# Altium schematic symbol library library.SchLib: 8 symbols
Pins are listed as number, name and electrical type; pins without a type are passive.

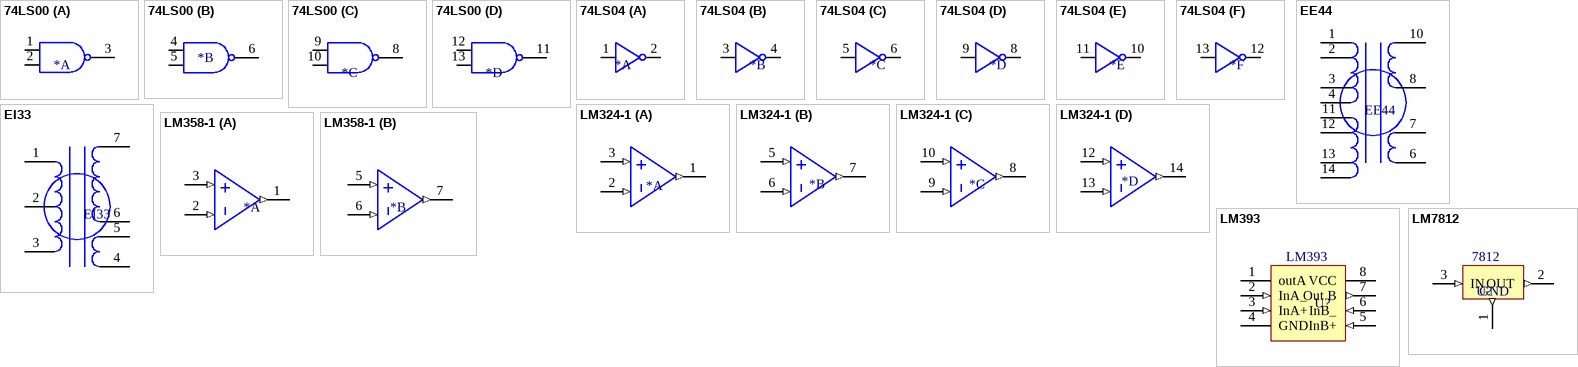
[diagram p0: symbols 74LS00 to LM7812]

## 74LS00
designator *
part A pins: 1 (power), 2 (power), 3 (power), 7 GND (power) hidden to GND, 14 VCC+5V (power) hidden to VCC+5V
part B pins: 4 (power), 5 (power), 6 (power)
part C pins: 8 (power), 9 (power), 10 (power)
part D pins: 11 (power), 12 (power), 13 (power)

## 74LS04
designator *
part A pins: 1 (power), 2 (power), 7 GND (power) hidden to GND, 14 VCC+5v (power) hidden to VCC+5V
part B pins: 3 (power), 4 (power)
part C pins: 5 (power), 6 (power)
part D pins: 8 (power), 9 (power)
part E pins: 10 (power), 11 (power)
part F pins: 12 (power), 13 (power)

## EE44
designator EE44
footprint EE44; pin to pad 10>9
pins: 1 (power), 2 (power), 3 (power), 4 (power), 6 (power), 7 (power), 8 (power), 10 (power), 11 (power), 12 (power), 13 (power), 14 (power)

## EI33
designator EI33
pins: 1 (power), 2 (power), 3 (power), 4 (power), 5 (power), 6 (power), 7 (power)

## LM324-1
designator *
part A pins: 1 OUT1 (out), 2 IN1(-) (in), 3 IN1(+) (in), 4 VCC (power) hidden to VCC, 11 GND (power) hidden to GND
part B pins: 5 IN2(+) (in), 6 IN2(-) (in), 7 OUT2 (out)
part C pins: 8 OUT3 (out), 9 IN3(-) (in), 10 IN3(+) (in)
part D pins: 12 IN4(+) (in), 13 IN4(-) (in), 14 OUT4 (out)

## LM358-1
designator *
part A pins: 1 OUT1 (out), 2 IN1(-) (in), 3 IN1(+) (in), 4 GND (in) hidden to GND, 8 VCC (in) hidden to VCC
part B pins: 5 IN2(+) (in), 6 IN2(-) (in), 7 OUT2 (out)

## LM393
designator U?
footprint Model Name (Model Description)
pins: 1 outA, 2 InA_ (in), 3 InA+ (in), 4 GND (power), 5 InB+ (in), 6 InB_ (in), 7 Out B (out), 8 VCC (power)

## LM7812
designator U?, comment 7812
pins: 1 GND (out), 2 OUT (out), 3 IN (in)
